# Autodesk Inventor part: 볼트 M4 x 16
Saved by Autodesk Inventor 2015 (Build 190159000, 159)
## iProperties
Created: 2025-08
Part Number: 볼트 M4 x 16
Material: 일반
Document SubType Name: Modeling
Designer: user
Density: 1 g/cm^3
Appearance: 기본값
Author: jhkim
Description: 6각 소켓 머리 캡 나사
Creation Date: 2025-08-05
Sending System: Autodesk Inventor 2026
Preprocessor: ST-DEVELOPER v20.1
Author: user
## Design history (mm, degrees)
node "볼트 M4 x 161"
body "Solid1"
node "기준1"
